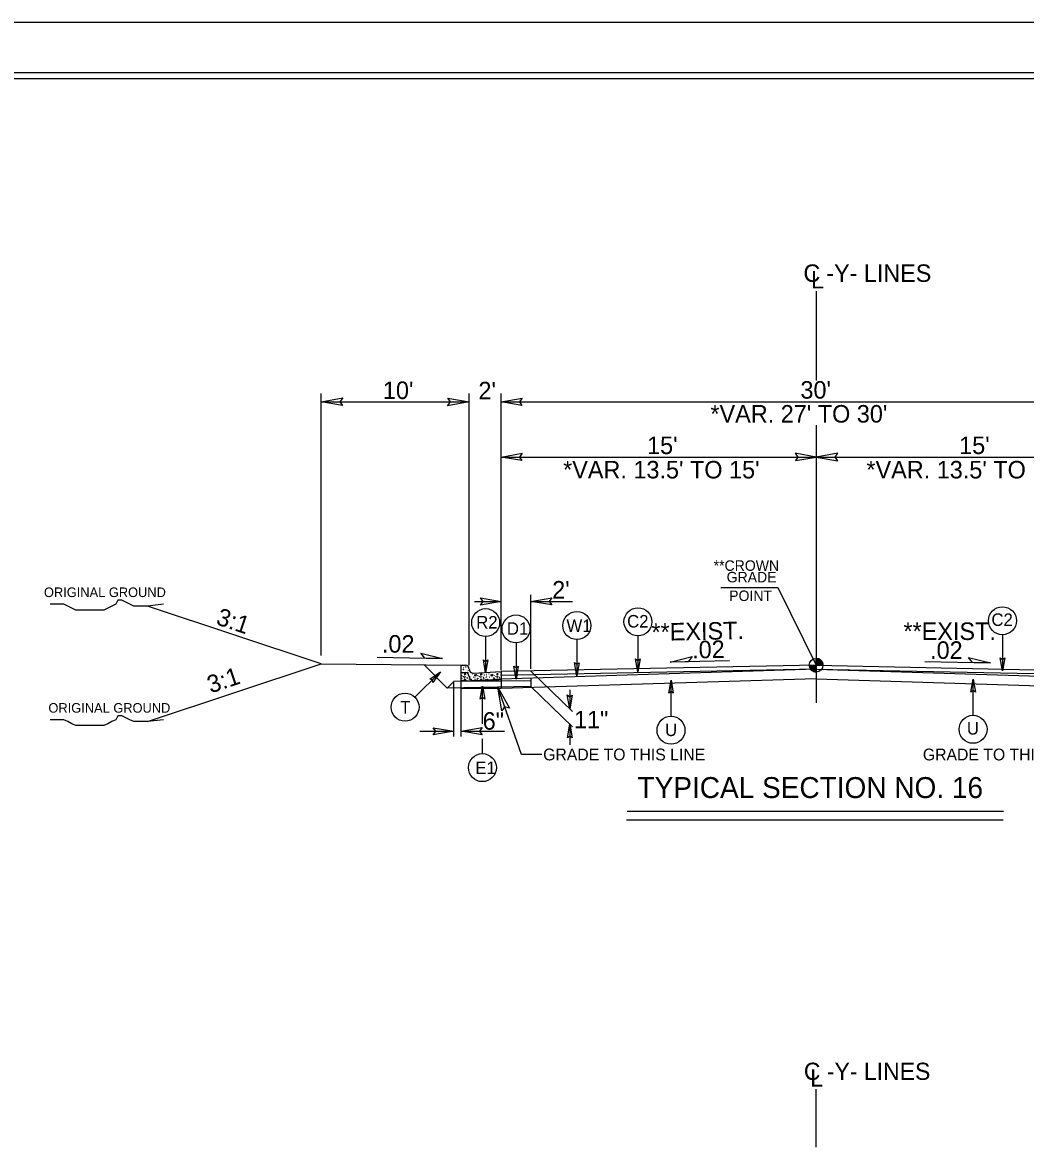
# Model space of a CAD drawing. Extents: x 957297 to 961629, y 830661 to 840840.
# Drawn here: x 959084 to 959531, y 832569 to 833070 of the extents above; entities that cross this region are included whole.
import ezdxf

# ---------------------------------------------------------------- set-up
doc = ezdxf.new("R2010")
doc.units = 0
for name, color, linetype in [('Default', 7, 'Continuous'), ('Old_Level_1', 7, 'Continuous'), ('Old_Level_11', 7, 'Continuous'), ('Old_Level_21', 7, 'Continuous'), ('Old_Level_3', 7, 'Continuous'), ('Prop Dimension Text', 7, 'Continuous'), ('Sheet Plot Border Inside CELL', 7, 'Continuous'), ('Sheet Plot Border Outside CELL', 7, 'Continuous'), ('Sheet Typical CELL', 7, 'Continuous'), ('Typical ID Circle CELL', 7, 'Continuous'), ('Typical Terminator CELL', 7, 'Continuous'), ('Typical Text Grade Point CELL', 7, 'Continuous'), ('Typical Text ID Circle CELL', 7, 'Continuous')]:
    doc.layers.add(name, color=color, linetype=linetype)

msp = doc.modelspace()

# ---------------------------------------------------------------- linework, layer by layer
at = {"layer": 'Default'}
for p, q in [((959437.72, 832950.23), (959437.72, 832910.49)), ((959437.72, 832890.61), (959437.72, 832767.06)), ((959437.72, 832569.23), (959437.72, 832595.08))]:
    msp.add_line(p, q, dxfattribs=at)
at = {"layer": 'Old_Level_1'}
for p, q in [((959217.28, 832788.06), (959217.28, 832904.62)), ((959283.31, 832783.78), (959283.31, 832904.62)), ((959297.55, 832781.58), (959297.55, 832904.62)), ((959217.28, 832900.98), (959283.31, 832900.98)), ((959297.55, 832900.98), (959577.94, 832900.98)), ((959297.5, 832876.42), (959437.72, 832876.42)), ((959437.72, 832876.42), (959577.94, 832876.42)), ((959310.76, 832782.15), (959310.76, 832815.11)), ((959217.28, 832784.37), (959140.09, 832810.1)), ((959285.62, 832812.18), (959297.55, 832812.18)), ((959310.76, 832812.18), (959329.18, 832812.18)), ((959140.09, 832758.64), (959217.28, 832784.37)), ((959217.28, 832784.37), (959279.75, 832783.74)), ((959242.22, 832787.32), (959271.44, 832786.74)), ((959273.48, 832773.58), (959263.16, 832783.91)), ((959437.72, 832783.73), (959297.55, 832780.89)), ((959399.11, 832785.7), (959372.73, 832785.17)), ((959434.66, 832783.72), (959437.72, 832783.72)), ((959437.72, 832783.72), (959437.72, 832786.78)), ((959437.72, 832783.73), (959577.94, 832780.89)), ((959440.78, 832783.72), (959437.72, 832783.72)), ((959437.72, 832780.67), (959437.72, 832783.72)), ((959437.72, 832783.72), (959437.72, 832780.67)), ((959486.07, 832785.43), (959515.29, 832784.84)), ((959279.75, 832773.33), (959279.75, 832780.15)), ((959280.06, 832780.46), (959281.54, 832780.46)), ((959437.72, 832782), (959297.55, 832779.17)), ((959437.72, 832782), (959297.55, 832777.61)), ((959310.76, 832781.16), (959329.23, 832763.23)), ((959437.72, 832782), (959577.94, 832779.17)), ((959437.72, 832782), (959577.94, 832777.61)), ((959276.45, 832776.55), (959273.48, 832773.58)), ((959310.76, 832774.34), (959273.48, 832773.58)), ((959279.75, 832776.62), (959276.45, 832776.55)), ((959276.45, 832752.06), (959276.45, 832776.1)), ((959279.75, 832752.06), (959279.75, 832775.82)), ((959297.55, 832773.33), (959279.75, 832773.33)), ((959285.16, 832776.99), (959297.55, 832777.61)), ((959306.5, 832744.04), (959295.97, 832774.04)), ((959437.72, 832777.73), (959297.55, 832773.33)), ((959297.55, 832777.61), (959297.55, 832773.33)), ((959310.76, 832776.88), (959297.55, 832776.62)), ((959310.76, 832778.02), (959310.76, 832774.34)), ((959310.76, 832774.34), (959329.23, 832756.41)), ((959437.72, 832777.73), (959577.88, 832773.33)), ((959328.02, 832772.77), (959328.02, 832764.41)), ((959261.26, 832754.36), (959276.45, 832754.36)), ((959279.75, 832754.36), (959299.02, 832754.36)), ((959328.08, 832757.51), (959328.09, 832748.29)), ((959315.54, 832744.04), (959306.5, 832744.04)), ((959521.22, 832718.6), (959353.52, 832718.6)), ((959520.94, 832714.79), (959353.24, 832714.79))]:
    msp.add_line(p, q, dxfattribs=at)
for points in [[(959434.68, 832783.72), (959434.68, 832783.4)], [(959434.74, 832783.72), (959434.74, 832783.03)], [(959434.8, 832783.72), (959434.8, 832782.81)], [(959434.86, 832783.72), (959434.86, 832782.63)], [(959434.93, 832783.72), (959434.93, 832782.49)], [(959434.99, 832783.72), (959434.99, 832782.36)], [(959435.05, 832783.72), (959435.05, 832782.24)], [(959435.11, 832783.72), (959435.11, 832782.13)], [(959435.17, 832783.72), (959435.17, 832782.05)], [(959435.23, 832783.72), (959435.23, 832781.95)], [(959435.3, 832783.72), (959435.3, 832781.86)], [(959435.36, 832783.72), (959435.36, 832781.8)], [(959435.42, 832783.72), (959435.42, 832781.73)], [(959435.47, 832783.72), (959435.47, 832781.65)], [(959435.53, 832783.72), (959435.53, 832781.58)], [(959435.6, 832783.72), (959435.6, 832781.53)], [(959435.66, 832783.72), (959435.66, 832781.48)], [(959435.72, 832783.72), (959435.72, 832781.42)], [(959435.78, 832783.72), (959435.78, 832781.37)], [(959435.85, 832783.72), (959435.85, 832781.31)], [(959435.9, 832783.72), (959435.9, 832781.27)], [(959435.96, 832783.72), (959435.96, 832781.23)], [(959436.02, 832783.72), (959436.02, 832781.19)], [(959436.09, 832783.72), (959436.09, 832781.13)], [(959436.15, 832783.72), (959436.15, 832781.1)], [(959436.21, 832783.72), (959436.21, 832781.06)], [(959436.28, 832783.72), (959436.28, 832781.03)], [(959436.33, 832783.72), (959436.33, 832781.01)], [(959436.39, 832783.72), (959436.39, 832780.97)], [(959436.46, 832783.72), (959436.46, 832780.94)], [(959436.52, 832783.72), (959436.52, 832780.92)], [(959436.58, 832783.72), (959436.58, 832780.88)], [(959436.64, 832783.72), (959436.64, 832780.87)], [(959436.7, 832783.72), (959436.7, 832780.85)], [(959436.75, 832783.72), (959436.75, 832780.82)], [(959436.82, 832783.72), (959436.82, 832780.81)], [(959436.88, 832783.72), (959436.88, 832780.79)], [(959436.94, 832783.72), (959436.94, 832780.77)], [(959437, 832783.72), (959437, 832780.76)], [(959437.07, 832783.72), (959437.07, 832780.74)], [(959437.13, 832783.72), (959437.13, 832780.72)], [(959437.19, 832783.72), (959437.19, 832780.72)], [(959437.25, 832783.72), (959437.25, 832780.71)], [(959437.31, 832783.72), (959437.31, 832780.69)], [(959437.38, 832783.72), (959437.38, 832780.69)], [(959437.44, 832783.72), (959437.44, 832780.69)], [(959437.5, 832783.72), (959437.5, 832780.67)], [(959437.56, 832783.72), (959437.56, 832780.67)], [(959437.61, 832783.72), (959437.61, 832780.67)], [(959437.67, 832783.72), (959437.67, 832780.67), (959437.67, 832780.67)], [(959437.76, 832786.78), (959437.76, 832786.78), (959437.76, 832783.72)], [(959437.81, 832786.78), (959437.81, 832783.72)], [(959437.87, 832786.78), (959437.87, 832783.72)], [(959437.94, 832786.77), (959437.94, 832783.72)], [(959438, 832786.77), (959438, 832783.72)], [(959438.06, 832786.77), (959438.06, 832783.72)], [(959438.12, 832786.75), (959438.12, 832783.72)], [(959438.18, 832786.75), (959438.18, 832783.72)], [(959438.23, 832786.73), (959438.23, 832783.72)], [(959438.3, 832786.73), (959438.3, 832783.72)], [(959438.36, 832786.72), (959438.36, 832783.72)], [(959438.42, 832786.7), (959438.42, 832783.72)], [(959438.49, 832786.68), (959438.49, 832783.72)], [(959438.55, 832786.66), (959438.55, 832783.72)], [(959438.61, 832786.65), (959438.61, 832783.72)], [(959438.67, 832786.63), (959438.67, 832783.72)], [(959438.74, 832786.61), (959438.73, 832783.72)], [(959438.79, 832786.59), (959438.79, 832783.72)], [(959438.85, 832786.57), (959438.85, 832783.72)], [(959438.92, 832786.54), (959438.92, 832783.72)], [(959438.98, 832786.52), (959438.98, 832783.72)], [(959439.04, 832786.48), (959439.04, 832783.72)], [(959439.09, 832786.46), (959439.09, 832783.72)], [(959439.15, 832786.44), (959439.15, 832783.72)], [(959439.21, 832786.4), (959439.21, 832783.72)], [(959439.28, 832786.36), (959439.28, 832783.72)], [(959439.34, 832786.32), (959439.34, 832783.72)], [(959439.4, 832786.28), (959439.4, 832783.72)], [(959439.47, 832786.23), (959439.47, 832783.72)], [(959439.52, 832786.2), (959439.52, 832783.72)], [(959439.59, 832786.15), (959439.59, 832783.72)], [(959439.65, 832786.1), (959439.65, 832783.72)], [(959439.71, 832786.06), (959439.71, 832783.72)], [(959439.77, 832786), (959439.77, 832783.72)], [(959439.83, 832785.93), (959439.83, 832783.72)], [(959439.9, 832785.87), (959439.9, 832783.72)], [(959439.95, 832785.81), (959439.95, 832783.72)], [(959440.01, 832785.75), (959440.01, 832783.72)], [(959440.07, 832785.68), (959440.07, 832783.72)], [(959440.13, 832785.59), (959440.13, 832783.72)], [(959440.2, 832785.52), (959440.2, 832783.72)], [(959440.26, 832785.43), (959440.26, 832783.72)], [(959440.32, 832785.34), (959440.32, 832783.72)], [(959440.38, 832785.24), (959440.38, 832783.72)], [(959440.44, 832785.13), (959440.44, 832783.72)], [(959440.5, 832784.98), (959440.5, 832783.72)], [(959440.57, 832784.84), (959440.57, 832783.72)], [(959440.63, 832784.68), (959440.63, 832783.72)], [(959440.69, 832784.47), (959440.69, 832783.72)], [(959440.75, 832784.16), (959440.75, 832783.72)]]:
    msp.add_lwpolyline(points, dxfattribs=at)
msp.add_circle((959437.72, 832783.73), 3.06, dxfattribs=at)
for centre, radius, start, end in [((959437.72, 832783.73), 3.06, 179.9905, 269.9905), ((959437.72, 832783.73), 3.06, 359.9905, 89.9905), ((959280.06, 832780.15), 0.309, 90, 180), ((959281.54, 832778.68), 1.78, 1.0734, 90), ((959285.07, 832778.75), 1.76, 181.0734, 272.8624)]:
    msp.add_arc(centre, radius, start, end, dxfattribs=at)
at = {"layer": 'Old_Level_11'}
for p, q in [((959263.44, 832786.9), (959261.7, 832789.15)), ((959261.7, 832789.15), (959271.44, 832786.74)), ((959271.44, 832786.74), (959263.44, 832786.9)), ((959372.73, 832785.17), (959382.49, 832787.59)), ((959380.75, 832785.33), (959372.73, 832785.17)), ((959382.49, 832787.59), (959380.75, 832785.33)), ((959507.28, 832785), (959505.55, 832787.26)), ((959505.55, 832787.26), (959515.29, 832784.84)), ((959515.29, 832784.84), (959507.28, 832785))]:
    msp.add_line(p, q, dxfattribs=at)
for points in [[(959226.88, 832899.33), (959217.28, 832900.98), (959226.94, 832902.69), (959225.71, 832900.98)], [(959273.71, 832902.64), (959283.31, 832900.98), (959273.65, 832899.27), (959274.88, 832900.98)], [(959447.33, 832878.08), (959437.72, 832876.42), (959447.39, 832874.7), (959446.16, 832876.42)], [(959297.74, 832763.45), (959295.97, 832774.04), (959301.25, 832764.62), (959299.04, 832765.29)]]:
    msp.add_lwpolyline(points, close=True, dxfattribs=at)
at = {"layer": 'Old_Level_21'}
for points in [[(959147.18, 832810.98), (959140.09, 832810.1), (959138.31, 832810.1), (959135.65, 832810.1), (959133.88, 832810.1), (959132.11, 832810.98), (959130.33, 832811.88), (959128.56, 832812.76), (959126.78, 832812.76), (959125.89, 832810.98), (959124.12, 832810.1), (959122.35, 832809.2), (959120.58, 832808.33), (959118.8, 832808.33), (959117.03, 832808.33), (959115.25, 832808.33), (959113.48, 832808.33), (959111.71, 832808.33), (959109.94, 832808.33), (959108.16, 832808.33), (959106.39, 832809.2), (959104.62, 832810.1), (959102.85, 832810.98), (959100.18, 832810.98), (959098.41, 832810.98), (959096.63, 832810.98)], [(959147.18, 832759.52), (959140.09, 832758.64), (959138.31, 832758.64), (959135.65, 832758.64), (959133.88, 832758.64), (959132.11, 832759.52), (959130.33, 832760.41), (959128.56, 832761.29), (959126.78, 832761.29), (959125.89, 832759.52), (959124.12, 832758.64), (959122.35, 832757.74), (959120.58, 832756.87), (959118.8, 832756.87), (959117.03, 832756.87), (959115.25, 832756.87), (959113.48, 832756.87), (959111.71, 832756.87), (959109.94, 832756.87), (959108.16, 832756.87), (959106.39, 832757.74), (959104.62, 832758.64), (959102.85, 832759.52), (959100.18, 832759.52), (959098.41, 832759.52), (959096.63, 832759.52)]]:
    msp.add_lwpolyline(points, dxfattribs=at)
at = {"layer": 'Old_Level_3'}
for p, q in [((959279.75, 832780.18), (959279.75, 832783.44)), ((959280.06, 832783.74), (959281.54, 832783.74)), ((959279.75, 832776.62), (959279.75, 832780.18)), ((959281.12, 832779.93), (959281.12, 832779.31)), ((959281.75, 832779.9), (959281.12, 832779.93)), ((959281.12, 832779.31), (959281.75, 832779.9)), ((959283.46, 832781.55), (959283.34, 832781.39)), ((959283.34, 832781.39), (959283.5, 832781.42)), ((959285.16, 832780.28), (959297.55, 832780.89)), ((959285.16, 832780.28), (959285.16, 832780.28)), ((959285.65, 832779.5), (959285.75, 832778.97)), ((959286.54, 832779.25), (959285.65, 832779.5)), ((959285.75, 832778.97), (959286.54, 832779.25)), ((959288.35, 832779.93), (959288.35, 832779.31)), ((959288.98, 832779.9), (959288.35, 832779.93)), ((959288.35, 832779.31), (959288.98, 832779.9)), ((959292.88, 832779.5), (959292.98, 832778.97)), ((959293.77, 832779.25), (959292.88, 832779.5)), ((959292.98, 832778.97), (959293.77, 832779.25)), ((959295.58, 832779.93), (959295.58, 832779.31)), ((959296.2, 832779.9), (959295.58, 832779.93)), ((959295.58, 832779.31), (959296.2, 832779.9)), ((959297.55, 832780.89), (959297.55, 832776.62)), ((959297.55, 832776.62), (959279.75, 832776.62)), ((959281.03, 832777.03), (959281.53, 832777.73)), ((959281.71, 832777.07), (959281.03, 832777.03)), ((959281.53, 832777.73), (959281.71, 832777.07)), ((959285.45, 832776.74), (959285.81, 832777.39)), ((959286.41, 832776.97), (959285.45, 832776.74)), ((959285.81, 832777.39), (959286.41, 832776.97)), ((959288.26, 832777.03), (959288.75, 832777.73)), ((959288.94, 832777.07), (959288.26, 832777.03)), ((959288.75, 832777.73), (959288.94, 832777.07)), ((959292.68, 832776.74), (959293.04, 832777.39)), ((959293.64, 832776.97), (959292.68, 832776.74)), ((959293.04, 832777.39), (959293.64, 832776.97)), ((959295.48, 832777.03), (959295.98, 832777.73)), ((959296.17, 832777.07), (959295.48, 832777.03)), ((959295.98, 832777.73), (959296.17, 832777.07))]:
    msp.add_line(p, q, dxfattribs=at)
for centre in [(959279.81, 832781.88), (959279.91, 832779.11), (959280.5, 832780.39), (959280.63, 832781.78), (959280.66, 832778.68), (959280.8, 832782.58), (959281.49, 832778.78), (959281.72, 832782.97), (959281.89, 832781.98), (959282.35, 832778.41), (959282.58, 832780.59), (959282.88, 832779.4), (959282.91, 832782.84), (959282.94, 832781.45), (959283.54, 832778.32), (959283.64, 832778.61), (959283.67, 832779.47), (959283.77, 832780.56), (959284.83, 832779.9), (959285.12, 832778.45), (959286.38, 832779.73), (959287.14, 832779.11), (959287.89, 832778.68), (959288.72, 832778.78), (959289.58, 832778.41), (959290.11, 832779.4), (959290.77, 832778.32), (959290.86, 832778.61), (959290.9, 832779.47), (959292.05, 832779.9), (959292.35, 832778.45), (959293.61, 832779.73), (959294.37, 832779.11), (959294.95, 832780.39), (959295.12, 832778.68), (959295.94, 832778.78), (959296.8, 832778.41), (959297.03, 832780.59), (959297.33, 832779.4), (959279.95, 832776.77), (959280.04, 832777.96), (959280.5, 832777.03), (959281.23, 832778.19), (959282.51, 832777.82), (959283.37, 832777.33), (959284.1, 832777.49), (959285.82, 832778.15), (959286.84, 832777.59), (959286.94, 832778.15), (959287.17, 832776.77), (959287.26, 832777.96), (959287.73, 832777.03), (959288.45, 832778.19), (959289.74, 832777.82), (959290.6, 832777.33), (959291.33, 832777.49), (959293.05, 832778.15), (959294.07, 832777.59), (959294.17, 832778.15), (959294.4, 832776.77), (959294.49, 832777.96), (959294.95, 832777.03), (959295.68, 832778.19), (959296.97, 832777.82)]:
    msp.add_circle(centre, 0.0464, dxfattribs=at)
for centre, radius, start, end in [((959280.06, 832783.44), 0.309, 90, 180), ((959279.95, 832783.66), 0.0464, 259.6531, 10.3469), ((959281.54, 832781.97), 1.78, 1.0734, 90), ((959285.07, 832782.03), 1.76, 181.0734, 272.8624), ((959287.73, 832780.39), 0.0464, 167.7795, 17.938), ((959291, 832780.56), 0.0464, 169.8374, 15.8801), ((959279.71, 832778.15), 0.0464, 330.4173, 29.5827)]:
    msp.add_arc(centre, radius, start, end, dxfattribs=at)
at = {"layer": 'Sheet Plot Border Inside CELL'}
msp.add_lwpolyline([(960390.3, 833047.34), (958723.8, 833047.34), (958723.8, 831992.24), (960390.3, 831992.24)], close=True, dxfattribs=at)
at = {"layer": 'Sheet Plot Border Outside CELL'}
msp.add_lwpolyline([(960394.8, 833069.79), (958710.8, 833069.79), (958710.8, 831969.79), (960394.8, 831969.79)], close=True, dxfattribs=at)
at = {"layer": 'Sheet Typical CELL'}
msp.add_lwpolyline([(960377.8, 833044.79), (958877.8, 833044.79), (958877.8, 831994.79), (960377.8, 831994.79)], close=True, dxfattribs=at)
at = {"layer": 'Typical ID Circle CELL'}
for p, q in [((959290.59, 832796.5), (959290.59, 832780.41)), ((959304.1, 832793.69), (959304.1, 832777.61)), ((959331.19, 832795.19), (959331.19, 832779.1)), ((959358.39, 832796.87), (959358.39, 832780.78)), ((959520.68, 832797.33), (959520.68, 832781.24)), ((959259.12, 832769.49), (959270.49, 832780.87)), ((959289.14, 832757.73), (959289.14, 832774.43)), ((959373.11, 832761.06), (959373.11, 832777.14)), ((959507.59, 832761.46), (959507.59, 832777.55)), ((959289.14, 832744.4), (959289.14, 832751.04))]:
    msp.add_line(p, q, dxfattribs=at)
for centre in [(959290.59, 832802.72), (959358.39, 832803.09), (959520.68, 832803.55), (959304.1, 832799.92), (959331.19, 832801.41), (959254.72, 832765.09), (959373.11, 832754.83), (959507.59, 832755.23), (959289.14, 832738.18)]:
    msp.add_circle(centre, 6.23, dxfattribs=at)
at = {"layer": 'Typical Terminator CELL'}
for points in [[(959306.72, 832899.39), (959297.5, 832900.98), (959306.77, 832902.62), (959305.59, 832900.98)], [(959306.72, 832874.83), (959297.5, 832876.42), (959306.77, 832878.06), (959305.59, 832876.42)], [(959428.5, 832874.83), (959437.72, 832876.42), (959428.44, 832878.06), (959429.62, 832876.42)], [(959288.33, 832813.77), (959297.55, 832812.18), (959288.28, 832810.54), (959289.46, 832812.18)], [(959319.98, 832810.59), (959310.76, 832812.18), (959320.03, 832813.82), (959318.85, 832812.18)], [(959291.58, 832786.18), (959290.59, 832780.41), (959289.56, 832786.21), (959290.59, 832785.47)], [(959305.09, 832783.37), (959304.1, 832777.61), (959303.08, 832783.4), (959304.1, 832782.67)], [(959332.18, 832784.87), (959331.19, 832779.1), (959330.16, 832784.9), (959331.19, 832784.16)], [(959359.39, 832786.55), (959358.39, 832780.78), (959357.37, 832786.58), (959358.39, 832785.84)], [(959521.67, 832787), (959520.68, 832781.24), (959519.66, 832787.04), (959520.68, 832786.3)], [(959265.72, 832777.49), (959270.49, 832780.87), (959267.12, 832776.04), (959266.92, 832777.29)], [(959288.15, 832768.67), (959289.14, 832774.43), (959290.17, 832768.64), (959289.14, 832769.38)], [(959372.12, 832771.38), (959373.11, 832777.14), (959374.13, 832771.35), (959373.11, 832772.08)], [(959506.6, 832771.78), (959507.59, 832777.55), (959508.62, 832771.75), (959507.59, 832772.49)], [(959329.07, 832770.47), (959328.02, 832764.41), (959326.94, 832770.51), (959328.02, 832769.73)], [(959267.23, 832755.94), (959276.45, 832754.36), (959267.18, 832752.72), (959268.36, 832754.36)], [(959288.97, 832752.77), (959279.75, 832754.36), (959289.03, 832755.99), (959287.85, 832754.36)], [(959327.04, 832751.44), (959328.08, 832757.51), (959329.16, 832751.41), (959328.09, 832752.19)]]:
    msp.add_lwpolyline(points, close=True, dxfattribs=at)
at = {"layer": 'Typical Text Grade Point CELL'}
for p, q in [((959395.28, 832818.28), (959420.61, 832818.28)), ((959420.61, 832818.28), (959437.72, 832783.72))]:
    msp.add_line(p, q, dxfattribs=at)

# ---------------------------------------------------------------- texts
at = {"layer": 'Old_Level_1'}
for s, height, p in [("30'", 7.801, (959430.74, 832902.4)), ("*VAR. 27' TO 30'", 7.8009, (959390.66, 832891.74)), ("15'", 7.801, (959362.45, 832877.72)), ("15'", 7.801, (959501.41, 832877.72)), ("*VAR. 13.5' TO 15'", 7.8009, (959325.07, 832866.88)), ("*VAR. 13.5' TO 15'", 7.8009, (959460.12, 832866.88)), ('GRADE TO THIS LINE', 5.2473, (959316.2, 832741.41)), ('GRADE TO THIS LINE', 5.2473, (959485.25, 832741.4)), ('TYPICAL SECTION NO. 16', 9.3239, (959358.21, 832724.64))]:
    msp.add_text(s, height=height, dxfattribs=at).set_placement(p)
at = {"layer": 'Old_Level_11'}
for s, height, p in [('**CROWN', 4.671, (959392.1, 832825.76)), ('GRADE', 4.671, (959397.89, 832820.63)), ('POINT', 4.671, (959399.02, 832812.33)), ('11"', 7.801, (959329.9, 832755.64))]:
    msp.add_text(s, height=height, dxfattribs=at).set_placement(p)
at = {"layer": 'Old_Level_21'}
for p in [(959093.93, 832814.09), (959095.92, 832762.63)]:
    msp.add_text('ORIGINAL GROUND', height=4.2722, dxfattribs=at).set_placement(p)
at = {"layer": 'Old_Level_3'}
for s, height, p in [("10'", 7.801, (959244.84, 832902.22)), ("2'", 7.801, (959287.37, 832902.07)), ('C -Y- LINES', 7.6574, (959432.26, 832599.21)), ('L', 7.66, (959435.09, 832596.18))]:
    msp.add_text(s, height=height, dxfattribs=at).set_placement(p)
for s, rotation, p in [('3:1', 341.5652, (959170.12, 832802.06)), ('.02', 359.4336, (959244.36, 832789.42)), ('3:1', 18.4348, (959168.15, 832771.15))]:
    msp.add_text(s, height=7.801, rotation=rotation, dxfattribs=at).set_placement(p)
at = {"layer": 'Prop Dimension Text'}
for s, height, rotation, p in [('C', 7.77, 0, (959432.07, 832954.36)), ('L', 7.77, 0, (959435.46, 832951.42)), ('-Y- LINES', 7.767, 0, (959442.27, 832954.37)), ("2'", 7.801, 0, (959320.2, 832813.43)), ('**EXIST.', 7.801, 1.1839, (959364.51, 832794.56)), ('**EXIST.', 7.801, 360, (959476.6, 832794.99)), ('.02', 7.801, 1.1839, (959382.6, 832786.75)), ('.02', 7.801, 360, (959488.47, 832786.59)), ('6"', 7.801, 0, (959289.25, 832755.06))]:
    msp.add_text(s, height=height, rotation=rotation, dxfattribs=at).set_placement(p)
at = {"layer": 'Typical Text ID Circle CELL'}
for s, height, p in [('R2', 5.572, (959286.39, 832800.09)), ('W1', 5.572, (959326.57, 832798.56)), ('C2', 5.572, (959353.58, 832800.54)), ('C2', 5.572, (959515.77, 832801.26)), ('D1', 5.572, (959300.04, 832797.29)), ('U', 5.57, (959370.46, 832752.21)), ('E1', 5.572, (959286, 832735.33))]:
    msp.add_text(s, height=height, dxfattribs=at).set_placement(p)
for s, p in [('T', (959252.54, 832762.22)), ('U', (959504.85, 832752.89))]:
    msp.add_text(s, height=5.57, rotation=360, dxfattribs=at).set_placement(p)

doc.saveas('drawing.dxf')
